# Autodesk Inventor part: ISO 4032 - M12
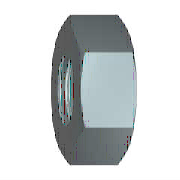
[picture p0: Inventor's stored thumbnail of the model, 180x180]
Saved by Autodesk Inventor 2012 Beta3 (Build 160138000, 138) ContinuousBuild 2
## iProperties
IsCustomPart: 0
Created: 2010-02
Part Number: ISO 4032 - M12
Material: Stainless Steel, 440C
Description: Hexagon nuts, style 1 - Product grades A and B
Document SubType Name: Modeling
Standard: ISO 4032
Designer: Thom Tremblay
Standard Revision: Third edition 1999-08-15
Standards Organization: ISO
Language: en-US
Size Designation: M12
Categories: <MemberInstance><Categories><Category DisplayName="Fasteners" InternalName="e4da775c-781d-43d5-af7c-5136215cf5a6" Mnemonic="FSTN"><Category DisplayName="Nuts" I
Density: 7.75 g/cm^3
Author: Thom Tremblay
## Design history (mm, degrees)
workaxis "Work Axis1"
workplane "Work Plane1"
sketch "Sketch1"
  geometry: L1 (-10.392, 0)-(-5.196, 9); L2 (-5.196, 9)-(5.196, 9); L3 (5.196, 9)-(10.392, 0); L4 (10.392, 0)-(5.196, -9); L5 (5.196, -9)-(-5.196, -9); L6 (-5.196, -9)-(-10.392, 0); 2 further points
  constraints: 12 end point, 1 coincident, 1 horizontal, 11 other
  dimensions: "d0" = 20.78461 distance of L3.end L1.start (= 1.1547 x SW)
extrude "Body" new body sketch "Sketch1" distance "d1" = 10.8 (= KOH); taper "d2" = 0 deg
revolve "Chamfer1" stored, may be unused: angle "d7" = 90 deg
sketch "Sketch3"
  geometry: 4 further points
  constraints: 1 coincident, 1 other
hole "Thread" sketch "Sketch3" diameter "d25" = 10.106; stored, may be unused: countersink angle "d29" = 82 deg, drill point angle "d31" = 118 deg; dims "d26" = 6, "d27" = 4, "d28" = 2, "d30" = 8
body "Solid1"
chamfer "Chamfer2" distance "d8" = 0.94722 (= -0.5 x GD1 + 0.5 x NND); stored, may be unused: angle "d9" = 30 deg, second distance "d40" = 0.94722 (= -0.5 x GD1 + 0.5 x NND)
chamfer "Chamfer3" distance "d10" = 0.94722 (= -0.5 x GD1 + 0.5 x NND); stored, may be unused: angle "d11" = 30 deg, second distance "d41" = 0.94722 (= -0.5 x GD1 + 0.5 x NND)
sketch "Sketch2"
  geometry: L1 (0, 5.196)-(0, 10.392) reference; L2 (0, 10.392)-(10.8, 10.392) reference; L3 (10.8, 5.196)-(10.8, 10.392) reference; L4 (-2.16, 0)-(12.96, 0) reference; L5 (1.208, 10.392)-(0, 8.3); L6 (9.592, 10.392)-(10.8, 8.3)
  constraints: 4 end point, 4 point on line
  dimensions: "d3" = 30 deg angle of L1 L5 (= ANG1); "d4" = 30 deg angle of L3 L6 (= ANG2); "d5" = 16.6 diameter of L5.end L4 (= SW0); "d6" = 16.6 diameter of L6.end L4 (= SW01)
other parameters: "ANG1" = 30 deg [user parameter; used in 1 equation term], "ANG2" = 30 deg [user parameter; used in 1 equation term], "NND" = 12 [user parameter; used in 4 equation terms], "KOH" = 10.8 [user parameter; used in 1 equation term], "SW" = 18 [user parameter; used in 2 equation terms], "SW0" = 16.6 [user parameter; used in 2 equation terms], "SW01" = 16.6 (= SW0) [user parameter; used in 1 equation term], "GD1" = 10.10557 (computed from THREADDIA, PTC, TOA) [user parameter; used in 4 equation terms], "d13" = 0, "d14" = 0, "d39" = 0, "d42" = 0, "GUL" = 0.94722 (= 0.541266 x PTC) [user parameter], "TPU" = 5.71429 (computed from PTC) [user parameter], "THREADDIA" = 12 [user parameter; used in 1 equation term], "TOA" = 30 deg [user parameter; used in 1 equation term], "PTC" = 1.75 [user parameter; used in 4 equation terms], "E0" = 20.79 (= 1.155 x SW) [user parameter], "GAL" = 0.94722 (= 0.541266 x PTC) [user parameter]
